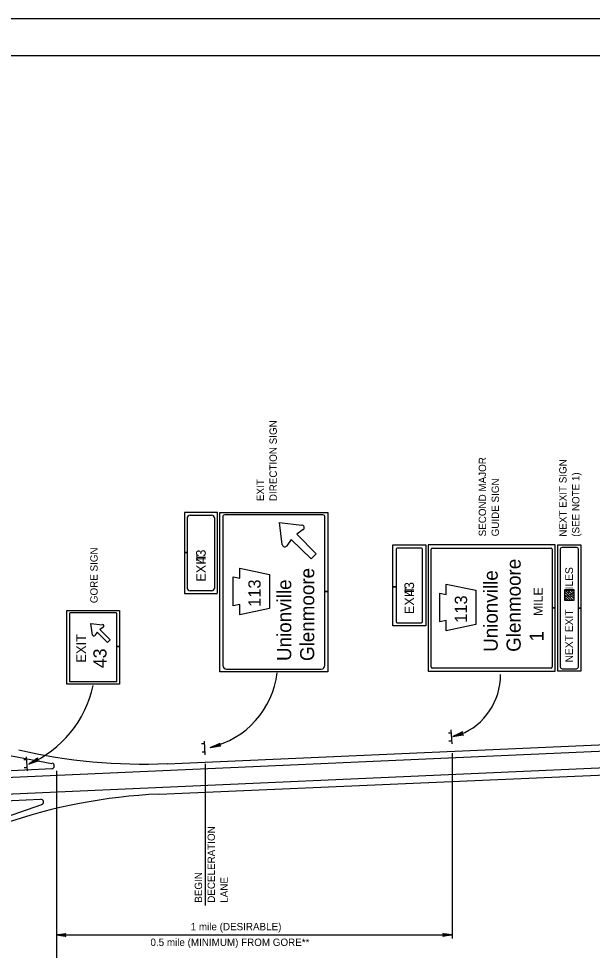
# Model space of a CAD drawing. Extents: x 644898 to 648326, y 298294 to 300670.
# Drawn here: x 646144 to 646378.1, y 300290.3 to 300670.5 of the extents above; entities that cross this region are included whole.
import ezdxf

# ---------------------------------------------------------------- set-up
doc = ezdxf.new("R2010")
doc.units = 0
for name, color, linetype in [('1', 7, 'Continuous'), ('2', 7, 'Continuous'), ('XCS-GRID-MIN', 7, 'Continuous')]:
    doc.layers.add(name, color=color, linetype=linetype)

msp = doc.modelspace()

# ---------------------------------------------------------------- linework, layer by layer
at = {"layer": '1'}
msp.add_line((645779.32, 300655.49), (646565.32, 300655.49), dxfattribs=at)
at = {"layer": '2'}
for p, q in [((646225.07, 300468.99), (646211.7, 300468.99)), ((646211.7, 300468.99), (646211.7, 300452.71)), ((646225.07, 300436.15), (646225.07, 300468.99)), ((646226.07, 300403.99), (646226.07, 300468.99)), ((646226.07, 300468.99), (646270.2, 300468.99)), ((646270.2, 300468.99), (646270.2, 300436.73)), ((646212.82, 300452.71), (646212.82, 300466.87)), ((646213.95, 300467.87), (646222.7, 300467.87)), ((646223.82, 300466.87), (646223.82, 300437.99)), ((646227.32, 300467.49), (646227.32, 300406.62)), ((646267.7, 300467.99), (646228.57, 300467.99)), ((646251.45, 300455.87), (646250.45, 300464.87)), ((646250.45, 300464.87), (646259.57, 300463.87)), ((646251.45, 300455.87), (646250.45, 300464.87)), ((646250.45, 300464.87), (646259.57, 300463.87)), ((646267.7, 300467.99), (646267.6, 300468.02)), ((646268.89, 300467.52), (646268.95, 300467.49)), ((646268.95, 300436.73), (646268.95, 300467.49)), ((646260.07, 300461.99), (646257.45, 300460.12)), ((646260.07, 300461.99), (646257.45, 300460.12)), ((646255.2, 300457.99), (646253.45, 300455.37)), ((646255.2, 300457.99), (646253.45, 300455.37)), ((646263.32, 300450.12), (646255.2, 300457.99)), ((646263.32, 300450.12), (646255.2, 300457.99)), ((646257.45, 300460.12), (646265.32, 300452.12)), ((646257.45, 300460.12), (646265.32, 300452.12)), ((646296.7, 300438.59), (646296.7, 300455.74)), ((646296.7, 300455.74), (646310.07, 300455.74)), ((646297.95, 300453.99), (646297.95, 300438.59)), ((646308.32, 300454.49), (646298.45, 300454.49)), ((646308.82, 300424.49), (646308.82, 300453.99)), ((646310.07, 300455.74), (646310.07, 300422.74)), ((646362.95, 300455.74), (646311.07, 300455.74)), ((646311.07, 300455.74), (646311.07, 300404.24)), ((646312.32, 300405.99), (646312.32, 300453.99)), ((646312.82, 300454.49), (646312.82, 300454.49)), ((646312.82, 300454.49), (646361.2, 300454.49)), ((646361.7, 300453.99), (646361.7, 300430.04)), ((646362.95, 300430.04), (646362.95, 300455.74)), ((646363.95, 300404.24), (646363.95, 300455.74)), ((646363.95, 300455.74), (646373.39, 300455.74)), ((646364.95, 300453.99), (646364.95, 300405.99)), ((646371.64, 300454.74), (646365.7, 300454.74)), ((646372.39, 300429.95), (646372.39, 300453.99)), ((646373.39, 300455.74), (646373.39, 300429.95)), ((646212.82, 300452.71), (646211.7, 300452.71)), ((646211.7, 300452.71), (646211.7, 300435.99)), ((646211.7, 300452.71), (646212.82, 300452.71)), ((646212.82, 300437.99), (646212.82, 300452.71)), ((646218.32, 300452.37), (646218.32, 300452.37)), ((646265.32, 300452.12), (646263.32, 300450.12)), ((646265.32, 300452.12), (646263.32, 300450.12)), ((646234.2, 300442.12), (646234.2, 300446.24)), ((646234.2, 300446.24), (646246.32, 300443.74)), ((646231.45, 300436.74), (646231.45, 300442.74)), ((646231.45, 300442.74), (646234.2, 300442.12)), ((646246.32, 300443.74), (646246.32, 300436.62)), ((646297.95, 300438.59), (646296.7, 300438.59)), ((646296.7, 300422.74), (646296.7, 300438.59)), ((646296.7, 300438.59), (646297.95, 300438.59)), ((646297.95, 300438.59), (646297.95, 300424.49)), ((646303.32, 300439.12), (646303.32, 300439.12)), ((646318.45, 300435.49), (646318.45, 300439.74)), ((646318.45, 300439.74), (646330.57, 300437.24)), ((646211.7, 300435.99), (646225.07, 300435.99)), ((646222.7, 300436.99), (646213.95, 300436.99)), ((646231.45, 300430.87), (646231.45, 300436.74)), ((646236.57, 300436.24), (646236.57, 300436.24)), ((646236.57, 300436.24), (646236.57, 300436.24)), ((646236.57, 300436.24), (646236.57, 300436.24)), ((646240.82, 300436.62), (646240.82, 300436.62)), ((646240.82, 300436.62), (646240.82, 300436.62)), ((646240.82, 300436.62), (646240.82, 300436.62)), ((646246.32, 300436.99), (646246.32, 300429.74)), ((646268.95, 300436.73), (646270.2, 300436.73)), ((646270.2, 300436.73), (646268.95, 300436.73)), ((646268.95, 300406.62), (646268.95, 300436.73)), ((646270.2, 300436.73), (646270.2, 300403.99)), ((646315.82, 300430.24), (646315.82, 300436.12)), ((646315.82, 300436.12), (646318.45, 300435.49)), ((646330.57, 300437.24), (646330.57, 300430.12)), ((646352.82, 300436.62), (646352.82, 300436.62)), ((646370.45, 300433.93), (646366.89, 300437.48)), ((646370.3, 300433.02), (646366.89, 300436.42)), ((646369.33, 300433.02), (646366.89, 300435.45)), ((646368.31, 300433.02), (646366.89, 300434.43)), ((646370.45, 300434.9), (646367.84, 300437.5)), ((646370.45, 300435.91), (646368.86, 300437.5)), ((646370.45, 300436.89), (646369.83, 300437.5)), ((646234.2, 300431.49), (646231.45, 300430.87)), ((646234.2, 300427.24), (646234.2, 300431.49)), ((646367.38, 300433.02), (646366.89, 300433.5)), ((646163.7, 300398.99), (646163.7, 300428.99)), ((646163.7, 300428.99), (646185.07, 300428.99)), ((646164.7, 300427.74), (646164.7, 300400.24)), ((646183.82, 300427.99), (646164.95, 300427.99)), ((646184.07, 300414.32), (646184.07, 300427.74)), ((646185.07, 300428.99), (646185.07, 300414.32)), ((646246.32, 300429.74), (646234.2, 300427.24)), ((646315.82, 300424.37), (646315.82, 300430.24)), ((646320.82, 300429.74), (646320.82, 300429.74)), ((646320.82, 300429.74), (646320.82, 300429.74)), ((646320.82, 300429.74), (646320.82, 300429.74)), ((646320.82, 300429.74), (646320.82, 300429.74)), ((646330.57, 300430.37), (646330.57, 300423.24)), ((646361.7, 300430.04), (646362.95, 300430.04)), ((646362.95, 300430.04), (646361.7, 300430.04)), ((646361.7, 300430.04), (646361.7, 300405.99)), ((646362.95, 300404.24), (646362.95, 300430.04)), ((646373.39, 300429.95), (646372.39, 300429.95)), ((646372.39, 300405.99), (646372.39, 300429.95)), ((646372.39, 300429.95), (646373.39, 300429.95)), ((646373.39, 300429.95), (646373.39, 300404.24)), ((646174.07, 300418.99), (646173.45, 300423.74)), ((646173.45, 300423.74), (646178.2, 300423.12)), ((646174.07, 300418.99), (646173.45, 300423.74)), ((646173.45, 300423.74), (646178.2, 300423.12)), ((646298.45, 300423.99), (646308.32, 300423.99)), ((646318.45, 300424.87), (646315.82, 300424.37)), ((646318.45, 300420.74), (646318.45, 300424.87)), ((646330.57, 300423.24), (646318.45, 300420.74)), ((646176.07, 300420.12), (646175.07, 300418.74)), ((646176.07, 300420.12), (646175.07, 300418.74)), ((646180.2, 300415.99), (646176.07, 300420.12)), ((646180.2, 300415.99), (646176.07, 300420.12)), ((646178.57, 300422.24), (646177.07, 300421.24)), ((646178.57, 300422.24), (646177.07, 300421.24)), ((646177.07, 300421.24), (646181.32, 300416.99)), ((646177.07, 300421.24), (646181.32, 300416.99)), ((646310.07, 300422.74), (646296.7, 300422.74)), ((646181.32, 300416.99), (646180.2, 300415.99)), ((646181.32, 300416.99), (646180.2, 300415.99)), ((646184.07, 300414.32), (646185.07, 300414.32)), ((646185.07, 300414.32), (646184.07, 300414.32)), ((646184.07, 300400.24), (646184.07, 300414.32)), ((646185.07, 300414.32), (646185.07, 300398.99)), ((646174.45, 300408.62), (646174.45, 300408.62)), ((646270.2, 300403.99), (646226.07, 300403.99)), ((646228.82, 300405.12), (646267.45, 300405.12)), ((646267.45, 300405.12), (646267.45, 300405.12)), ((646311.07, 300404.24), (646362.95, 300404.24)), ((646361.2, 300405.49), (646312.82, 300405.49)), ((646361.7, 300405.99), (646361.7, 300405.99)), ((646373.39, 300404.24), (646363.95, 300404.24)), ((646365.7, 300405.24), (646371.64, 300405.24)), ((646185.07, 300398.99), (646163.7, 300398.99)), ((646164.95, 300399.99), (646183.82, 300399.99)), ((646072.57, 300382.62), (646157.57, 300366.62)), ((646204.57, 300366.49), (646565.32, 300382.33)), ((646074.45, 300357.99), (646565.32, 300379.71)), ((646320.45, 300378.99), (646319.32, 300378.99)), ((646320.32, 300380.24), (646320.7, 300374.62)), ((646219.7, 300374.62), (646218.57, 300374.62)), ((646219.7, 300375.74), (646219.95, 300370.12)), ((646320.57, 300375.74), (646319.57, 300375.62)), ((646075.95, 300351.37), (646565.32, 300372.83)), ((646201.32, 300353.99), (646565.32, 300369.96)), ((646219.95, 300371.24), (646218.82, 300371.24)), ((646320.82, 300370.74), (646320.82, 300295.12)), ((646147.2, 300368.12), (646146.07, 300368.12)), ((646147.07, 300369.24), (646147.45, 300363.62)), ((646220.07, 300367.87), (646220.07, 300367.87)), ((646220.07, 300366.37), (646220.07, 300308.62)), ((646073.82, 300360.74), (646157.45, 300364.49)), ((646147.32, 300364.74), (646146.2, 300364.74)), ((646159.45, 300363.62), (646159.45, 300295.12)), ((646159.45, 300363.62), (646159.45, 300259.99)), ((646076.57, 300348.62), (646152.95, 300351.99)), ((646153.32, 300349.74), (646086.24, 300326.29)), ((646159.45, 300296.62), (646220.07, 300296.62)), ((646220.07, 300296.62), (646320.82, 300296.62))]:
    msp.add_line(p, q, dxfattribs=at)
msp.add_lwpolyline([(646370.45, 300433.02), (646366.89, 300433.02), (646366.89, 300437.5), (646370.45, 300437.5)], close=True, dxfattribs=at)
for points in [[(646325.26, 300378.27), (646325.1, 300378.5), (646321.15, 300377.55), (646325.26, 300378.27), (646325.48, 300378.15), (646321.15, 300377.55), (646324.96, 300379.01), (646324.97, 300379.29), (646321.15, 300377.55), (646325.15, 300379.62), (646324.97, 300379.29)], [(646226.32, 300373.74), (646226.07, 300373.99), (646222.2, 300373.12), (646226.32, 300373.74), (646226.45, 300373.62), (646222.2, 300373.12), (646225.82, 300374.37), (646225.95, 300374.62), (646222.2, 300373.12), (646226.2, 300374.87), (646225.95, 300374.62)], [(646151.95, 300367.62), (646151.7, 300367.74), (646148.2, 300366.37), (646151.95, 300367.62), (646152.32, 300367.62), (646148.2, 300366.37), (646151.57, 300368.24), (646151.57, 300368.49), (646148.2, 300366.37), (646151.7, 300368.87), (646151.57, 300368.49)], [(646162.95, 300296.12), (646162.82, 300296.37), (646159.45, 300296.62), (646162.95, 300296.12), (646163.2, 300295.99), (646159.45, 300296.62), (646162.82, 300296.74), (646162.95, 300296.99), (646159.45, 300296.62), (646163.2, 300297.24), (646162.95, 300296.99)], [(646317.32, 300297.12), (646317.45, 300296.87), (646320.82, 300296.62), (646317.32, 300297.12), (646317.07, 300297.24), (646320.82, 300296.62), (646317.45, 300296.49), (646317.32, 300296.24), (646320.82, 300296.62), (646317.07, 300295.99), (646317.32, 300296.24)]]:
    msp.add_lwpolyline(points, dxfattribs=at)
for centre, radius, start, end in [((646259.46, 300462.8), 1.06, 303.2476, 87.1543), ((646259.46, 300462.8), 1.06, 303.2476, 87.1543), ((646252.62, 300456.04), 1.06, 184.8591, 325.5247), ((646252.62, 300456.04), 1.06, 184.8591, 325.5247), ((646298.45, 300453.99), 0.5, 90, 180), ((646308.32, 300453.99), 0.5, 0, 90), ((646312.82, 300453.99), 0.5, 90, 180), ((646361.2, 300453.99), 0.5, 0, 90), ((646365.7, 300453.99), 0.75, 90, 180), ((646371.64, 300453.99), 0.75, 0, 90), ((646164.95, 300427.74), 0.25, 90, 180), ((646183.82, 300427.74), 0.25, 0, 90), ((646178.22, 300422.67), 0.559, 303.2476, 87.1543), ((646178.22, 300422.67), 0.559, 303.2476, 87.1543), ((646298.45, 300424.49), 0.5, 180, 270), ((646308.32, 300424.49), 0.5, 270, 360), ((646174.62, 300419.12), 0.559, 184.8591, 325.5247), ((646174.62, 300419.12), 0.559, 184.8591, 325.5247), ((646228.82, 300406.62), 1.5, 180, 270), ((646267.45, 300406.62), 1.5, 270, 0), ((646312.82, 300405.99), 0.5, 180, 270), ((646361.2, 300405.99), 0.5, 270, 0), ((646365.7, 300405.99), 0.75, 180, 270), ((646371.64, 300405.99), 0.75, 270, 0), ((646164.95, 300400.24), 0.25, 180, 270), ((646183.82, 300400.24), 0.25, 270, 0), ((646214.11, 300407.89), 35.66, 283.0899, 352.9849), ((646314.34, 300402.71), 26.27, 291.9056, 0.2667), ((646129.99, 300407.85), 45.35, 293.5698, 347.9262), ((646194.78, 300590.27), 223.94, 256.8911, 272.5187), ((646157.41, 300365.59), 1.12, 272.5188, 76.8911), ((646211.06, 300130.34), 223.94, 92.5187, 109.2633), ((646152.97, 300350.83), 1.12, 289.2634, 92.5188)]:
    msp.add_arc(centre, radius, start, end, dxfattribs=at)
for centre, major_axis, ratio, start_param, end_param in [((646213.92, 300466.85), (-1.16, 0), 0.890834, 4.712389, 6.283185), ((646222.72, 300466.85), (-1.16, 0), 0.890834, 3.141593, 4.712389), ((646228.55, 300467.52), (-1.29, 0), 0.384567, 4.712389, 6.283185), ((646267.6, 300467.52), (-1.29, 0), 0.384567, 3.141593, 4.712389), ((646213.92, 300438.04), (1.16, 0), 0.890834, 3.141593, 4.712389), ((646222.72, 300438.04), (1.16, 0), 0.890834, 4.712389, 6.283185)]:
    msp.add_ellipse(centre, major_axis=major_axis, ratio=ratio, start_param=start_param, end_param=end_param, dxfattribs=at)
at = {"layer": 'XCS-GRID-MIN'}
msp.add_lwpolyline([(645739.32, 300670.49), (646580.32, 300670.49), (646580.32, 300076.49), (645739.32, 300076.49)], close=True, dxfattribs=at)

# ---------------------------------------------------------------- texts
at = {"layer": '2'}
for s, height, p in [('DIRECTION SIGN', 3, (646249.32, 300473.62)), ('SECOND MAJOR', 3, (646334.7, 300459.24)), ('NEXT EXIT SIGN', 3, (646367.54, 300459.07)), ('(SEE NOTE 1)', 3, (646372.79, 300459.07)), ('EXIT', 3, (646244.07, 300473.62)), ('GUIDE SIGN', 3, (646339.95, 300459.24)), ('GORE SIGN', 3, (646176.2, 300431.99)), ('     43', 3.918, (646220.32, 300440.74)), ('EXIT ', 3.875, (646220.32, 300440.74)), ('Glenmoore', 5.743, (646348.82, 300412.12)), ('Glenmoore', 5.743, (646264.57, 300408.37)), ('NEXT EXIT    MILES', 3.1342, (646370.15, 300407.79)), ('Unionville', 5.743, (646339.45, 300412.12)), ('113', 5, (646242.7, 300430.49)), ('Unionville', 5.743, (646255.2, 300408.37)), ('     43', 3.918, (646305.32, 300427.49)), ('EXIT ', 3.875, (646305.32, 300427.49)), ('MILE', 3.749, (646357.82, 300426.74)), ('113', 5, (646326.95, 300423.99)), ('EXIT', 3.917, (646171.45, 300407.74)), ('  1 ', 5.743, (646358.2, 300412.12)), ('43  ', 5.375, (646179.82, 300405.49)), ('DECELERATION', 3, (646224.07, 300309.74)), ('BEGIN', 3, (646218.82, 300309.74)), ('LANE', 3, (646229.32, 300309.74))]:
    msp.add_text(s, height=height, rotation=90, dxfattribs=at).set_placement(p)
for s, p in [('1 mile (DESIRABLE)', (646214.18, 300298.5)), ('0.5 mile (MINIMUM) FROM GORE**', (646197.76, 300292.12))]:
    msp.add_text(s, height=3, dxfattribs=at).set_placement(p)

doc.saveas('drawing.dxf')
